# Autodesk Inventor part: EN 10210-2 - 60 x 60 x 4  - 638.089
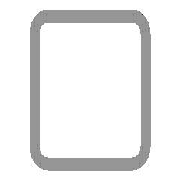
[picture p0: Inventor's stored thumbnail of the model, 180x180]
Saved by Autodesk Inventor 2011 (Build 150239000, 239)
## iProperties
IsCustomPart: 1
Created: 2010-02
Part Number: EN 10210-2 - 60 x 60 x 4  - 638.089
Material: Steel, Mild
Description: Tube 60*60*4
Document SubType Name: Modeling
Standard: DIN
Designer: PC
Standard Revision: 1997
Standards Organization: DIN
Language: en-US
Size Designation: 60 x 60 x 4
Categories: <MemberInstance><Categories><Category DisplayName="Structural Shapes" InternalName="089c4875-fa83-4c05-b084-43b9cc11f5ed" Mnemonic="GRDR"><CategoryParameter Dis
Stock Number: 60 x 60 x 4
Density: 7.86 g/cm^3
_CCFamilyMember: 20
_CCFamilyDisplayName: DIN EN 10219-2 (Square Hollow Section - Cold Formed) - Cold formed welded structural hollow sections of non-alloy and fine grain structural steel
_FrameMemberDoc: Frame Member File
_Version: 15.0.0
_GetPNFromCC: 1
G_L: 638.089 mm
G_W: 60.000 mm
G_H: 60.000 mm
+EAAF8082-8F4F-4B8B-BA37-61F5DEFF46F4+CUTDETAIL1: Cut
+1D7F05F0-FFAE-489B-9B9E-930555DBC6ED+CUTDETAIL2: Cut
Author: PC
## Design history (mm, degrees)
node "Start plane"
node "End plane"
sketch "Sketch"
  geometry: L1 (-30, -22)-(-30, 22); L2 (-22, 30)-(22, 30); L3 (30, 22)-(30, -22); L4 (22, -30)-(-22, -30); L5 (-22, 26)-(22, 26); L6 (26, 22)-(26, -22); L7 (22, -26)-(-22, -26); L8 (-26, -22)-(-26, 22); L9 (0, 44.32)-(0, -44.32) reference; L10 (-44.32, 0)-(44.32, 0) reference; A1 r 8 centre (-22, -22) between (-30, -22) and (-22, -30); A2 r 8 centre (-22, 22) between (-22, 30) and (-30, 22); A3 r 8 centre (22, 22) between (30, 22) and (22, 30); A4 r 8 centre (22, -22) between (22, -30) and (30, -22); A5 r 4 centre (-22, 22) between (-22, 26) and (-26, 22); A6 r 4 centre (22, 22) between (26, 22) and (22, 26); A7 r 4 centre (22, -22) between (22, -26) and (26, -22); A8 r 4 centre (-22, -22) between (-26, -22) and (-22, -26)
  constraints: 16 end point, 16 point on circle, 8 centre point, 8 tangent, 4 parallel, 3 equal radius, 2 perpendicular, 7 other
  dimensions: "d7" = 8 radius of A1 (= G_IR); "d10" = 60 distance between parallel lines of L2 L4 (= G_H); "d11" = 60 distance between parallel lines of L1 L3 (= G_W); "d12" = 4 distance between parallel lines of L3 L6 (= G_T); "d15" = 30 distance between parallel lines of L2 L10 (= 0.5 x d10); "d16" = 30 distance between parallel lines of L9 L3 (= 0.5 x d11)
extrude "Body" new body sketch "Sketch" stored distance "d3" = 638.08871 (= G_L); taper "d4" = 0 deg
node "Driven Length"
  sketch "Sketch3"
    geometry: L1 (0, 0)-(10, 0) reference
    constraints: 2 end point, 1 horizontal
  workplane "Work Plane3"
  sketch "Sketch4"
    geometry: L1 (-2, 48.118)-(12, 48.118) reference; L2 (-2, 686.207)-(12, 686.207) reference
    dimensions: "d18" = 638.08871 distance between parallel lines of L1 L2 (derived)
workplane "Work Plane4"
split "Split1"
workplane "Work Plane5"
split "Split2"
body "Solid1"
other parameters: "G_W" = 60 [user parameter; used in 1 equation term], "G_H" = 60 [user parameter; used in 1 equation term], "G_T" = 4 [user parameter; used in 1 equation term], "G_IR" = 8 [user parameter; used in 1 equation term], "G_L" = 638.08871 (= d18) [user parameter; used in 1 equation term], "G_OFFSET_START" = -48.11789 [user parameter; used in 1 equation term], "G_OFFSET_END" = -48.11789 [user parameter; used in 1 equation term], "d13" = 48.11789 (= -G_OFFSET_START), "d14" = 686.20661 (= G_OFFSET_END + B_L), "B_L" = 734.3245 [user parameter; used in 1 equation term], "d17" = 90 deg
